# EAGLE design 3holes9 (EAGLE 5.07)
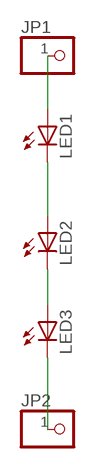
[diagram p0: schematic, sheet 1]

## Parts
JP1  PINHD-1X11MM6  [1X1MM8]
JP2  PINHD-1X11MM6  [1X1MM8]
LED1  LED1W1MM6  [1W1MM6]
LED2  LED1W1MM6  [1W1MM6]
LED3  LED1W1MM6  [1W1MM6]

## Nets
N$1: LED1.C LED2.A
N$2: LED2.C LED3.A
N$3: JP1.1 LED1.A
N$4: JP2.1 LED3.C

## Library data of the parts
JP1 JP2 = pinhead:PINHD-1X1: PIN HEADER
LED1-LED3 = led:LED: LED

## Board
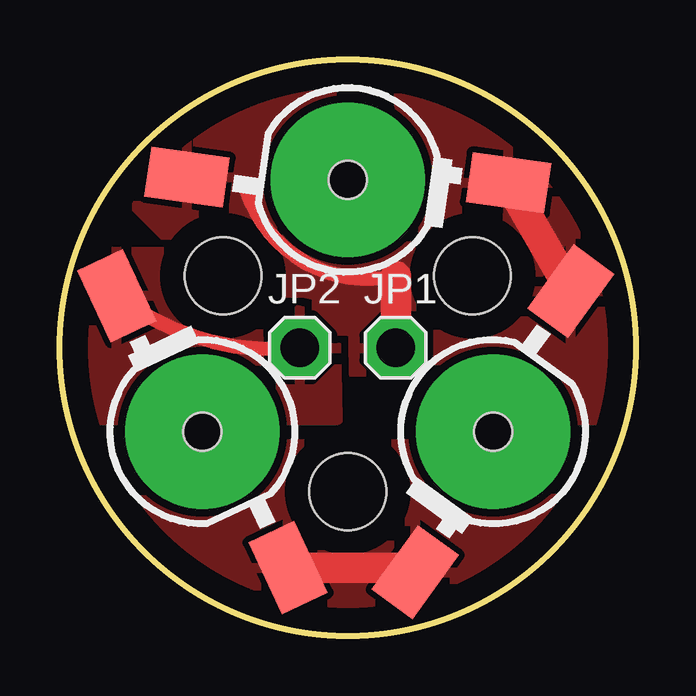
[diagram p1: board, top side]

Size 24 x 24 mm. Coordinates in mm from the lower left corner, seen from the top.
Outline: circle at 12,12 radius 12
Copper layers (1*16): Top 0.035mm / dielectric 1.5mm / Bottom 0.035mm
Design rules "default": minimum track width 10mil, minimum drill 24mil, track to track 8mil, track to pad 8mil, pad to pad 8mil, via to via 8mil, smd to smd 8mil, copper to edge 40mil, drill to drill 8mil, minimum pad ring 10mil, minimum via ring 8mil, stop-mask expansion 4mil, vias tented up to drill 0mil, thermal gap 10mil
Holes 3.2 mm at 17.2,15 12,6 6.8,15

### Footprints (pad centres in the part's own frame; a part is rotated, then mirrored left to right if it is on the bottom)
1X1MM8 = drill 1.6 pad 2.54 octagon: 1 0,0
1W1MM6 = smd 3.3 x 2.1: A -6.65,-0.82; C 6.65,0.82 | drill 1.6 pad 6.452 round: P$1 0,0 | hole 1.6: 0,0

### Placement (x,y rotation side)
JP1  14,12 0 top
JP2  10,12 0 top
LED1  12,19 352 top
LED2  18.06,8.5 234 top
LED3  5.94,8.5 115.2 top

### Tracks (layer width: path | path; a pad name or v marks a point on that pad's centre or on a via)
N$1
  Top 1.27: LED2.A LED1.C
  pour Top (isolate 0.305): 14,23 16,9 23,9 24,10 arc35 18,23
N$2
  Top 1.27: LED3.A 14.74,2.83 arc-90 LED2.C
  pour Top (isolate 0.305, rank 2): 3,8 21,8 21,5 arc-96 3,5
N$3
  Top 0.61: 7.8,18.5 arc84 14,15
  Top 1.27: 14,15 JP1.1
  pour Top (isolate 0.305, rank 2): 5,21 6,22 arc-51 15,23 15,12 14,11 10,11 3,18
N$4
  Top 0.61: LED3.C arc44 JP2.1
  pour Top (isolate 0.305): 1,16 1,9 11.6,9 11.5,13.2 8,14 6,16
